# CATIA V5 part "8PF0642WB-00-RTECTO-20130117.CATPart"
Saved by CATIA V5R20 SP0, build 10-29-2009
Part number: 8PF0642WB-00-RTECTO-20130117
Revision: ANY
Definition: UNKNOWN
Nomenclature: 8PF0642WB-00-RTECTO-20130117
Source: Unknown
Bounding box of the stored display mesh (mm): x 1758.686 to 1958.686, y 1414.697 to 1418.697, z 0 to 6
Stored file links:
  C:\Users\Utente\Desktop\IO LAVORO\3D X SITO CF\CUMSA\3D files PF\PF 0642WB\8PF0642WB-00-RTECTO-20130117.CATPart
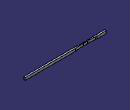
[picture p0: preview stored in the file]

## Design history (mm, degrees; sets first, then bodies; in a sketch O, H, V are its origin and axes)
Body1 "Cortar-Extruir1" (main body)
  Solid1: solid without history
